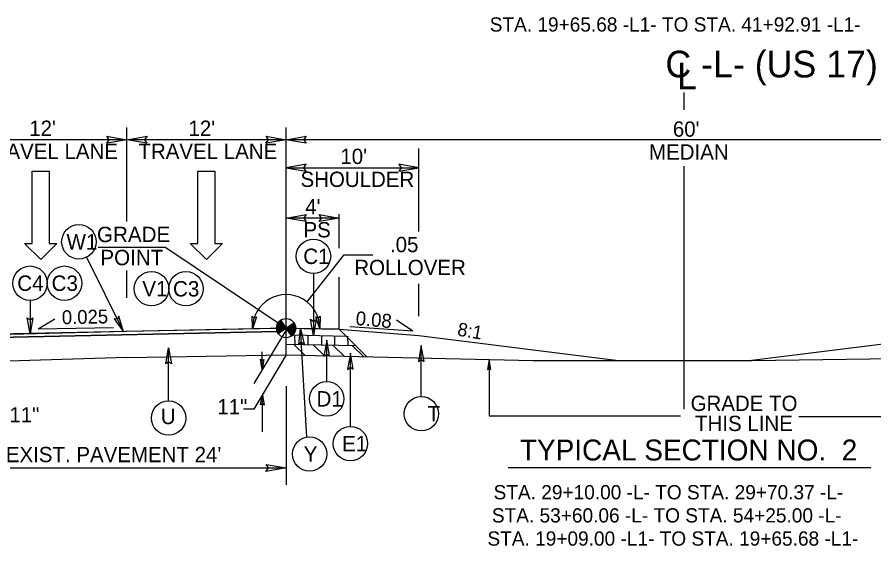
# Model space of a CAD drawing. Extents: x 2176024 to 2177225, y 75947 to 76635.
# Drawn here: x 2176725.6 to 2176790.1, y 76497.9 to 76537.7 of the extents above; entities that cross this region are included whole.
import ezdxf

# ---------------------------------------------------------------- set-up
doc = ezdxf.new("R2010")
doc.units = 0
for name, color, linetype in [('Exist XS Ground Line', 7, 'Continuous'), ('Old_Level_1', 7, 'Continuous'), ('Old_Level_11', 7, 'Continuous'), ('Old_Level_3', 7, 'Continuous'), ('Old_Level_4', 7, 'Continuous'), ('Prop Dimension', 7, 'Continuous'), ('Typical Curb CELL', 7, 'Continuous'), ('Typical Grade Point Symbol CELL', 7, 'Continuous'), ('Typical Pavement Slope CELL', 7, 'Continuous'), ('Typical Pavement Slope Information CELL', 7, 'Continuous'), ('Typical Shoulder Slope CELL', 7, 'Continuous'), ('Typical Slope Point Local CELL', 7, 'Continuous'), ('Typical Terminator CELL', 7, 'Continuous'), ('Typical Text General CELL', 7, 'Continuous'), ('Typical Text Label CELL', 7, 'Continuous')]:
    doc.layers.add(name, color=color, linetype=linetype)

msp = doc.modelspace()

# ---------------------------------------------------------------- linework, layer by layer
at = {"layer": 'Exist XS Ground Line'}
for q in [(2176721.841, 76511.705), (2176745.841, 76512.258)]:
    msp.add_line((2176733.841, 76512.056), q, dxfattribs=at)
at = {"layer": 'Old_Level_1'}
for p, q in [((2176746.512, 76513.046), (2176746.507, 76513.755)), ((2176747.51, 76513.024), (2176747.504, 76513.734)), ((2176748.543, 76513.003), (2176748.537, 76513.713)), ((2176749.524, 76512.981), (2176749.518, 76513.693)), ((2176750.505, 76512.957), (2176750.499, 76513.672)), ((2176747.287, 76512.213), (2176746.426, 76513.051)), ((2176748.725, 76512.193), (2176747.886, 76513.018)), ((2176750.204, 76512.16), (2176749.36, 76512.991)), ((2176751.694, 76512.117), (2176750.851, 76512.946)), ((2176762.567, 76503.771), (2176789.888, 76503.771))]:
    msp.add_line(p, q, dxfattribs=at)
at = {"layer": 'Old_Level_11'}
for p, q in [((2176736.776, 76520.349), (2176731.682, 76520.349)), ((2176736.776, 76520.349), (2176745.841, 76514.272)), ((2176730.802, 76519.616), (2176733.596, 76514.003)), ((2176750.159, 76519.771), (2176747.406, 76516.265)), ((2176752.368, 76519.771), (2176750.159, 76519.771)), ((2176747.896, 76518.39), (2176747.896, 76513.73)), ((2176726.55, 76516.363), (2176726.55, 76513.839)), ((2176747.41, 76506.064), (2176746.927, 76514.253)), ((2176748.905, 76510.241), (2176748.905, 76513.374)), ((2176736.983, 76508.794), (2176736.983, 76512.793)), ((2176756.029, 76509.115), (2176756.029, 76512.957)), ((2176750.685, 76506.87), (2176750.685, 76512.374))]:
    msp.add_line(p, q, dxfattribs=at)
for points in [[(2176726.757, 76515.039), (2176726.55, 76513.839), (2176726.337, 76515.045), (2176726.55, 76514.892)], [(2176732.876, 76514.985), (2176733.596, 76514.003), (2176733.249, 76515.178), (2176733.127, 76514.946)], [(2176748.103, 76514.93), (2176747.896, 76513.73), (2176747.683, 76514.937), (2176747.896, 76514.783)], [(2176746.791, 76513.043), (2176746.927, 76514.253), (2176747.211, 76513.061), (2176746.989, 76513.201)], [(2176749.111, 76512.174), (2176748.905, 76513.374), (2176748.691, 76512.168), (2176748.905, 76512.321)], [(2176736.776, 76511.593), (2176736.983, 76512.793), (2176737.196, 76511.587), (2176736.983, 76511.74)], [(2176756.236, 76511.757), (2176756.029, 76512.957), (2176755.816, 76511.75), (2176756.029, 76511.903)], [(2176750.892, 76511.174), (2176750.685, 76512.374), (2176750.472, 76511.167), (2176750.685, 76511.32)]]:
    msp.add_lwpolyline(points, close=True, dxfattribs=at)
for centre in [(2176730.224, 76520.777), (2176747.902, 76519.686), (2176726.55, 76517.659), (2176729.143, 76517.659), (2176735.699, 76517.238), (2176738.291, 76517.238), (2176748.905, 76508.945), (2176736.983, 76507.498), (2176756.029, 76507.819), (2176750.685, 76505.574), (2176747.61, 76504.783)]:
    msp.add_circle(centre, 1.296, dxfattribs=at)
msp.add_arc((2176745.841, 76514.272), 2.534, 358.80651, 181.19349, dxfattribs=at)
at = {"layer": 'Old_Level_4'}
for p, q in [((2176726.703, 76520.662), (2176726.703, 76526.094)), ((2176726.703, 76526.094), (2176727.984, 76526.094)), ((2176727.984, 76526.094), (2176727.984, 76520.662)), ((2176739.181, 76520.662), (2176739.181, 76526.094)), ((2176739.181, 76526.094), (2176740.462, 76526.094)), ((2176740.462, 76526.094), (2176740.462, 76520.662)), ((2176727.363, 76519.44), (2176726.121, 76520.662)), ((2176726.121, 76520.662), (2176726.703, 76520.662)), ((2176728.566, 76520.662), (2176727.363, 76519.44)), ((2176727.984, 76520.662), (2176728.566, 76520.662)), ((2176739.841, 76519.44), (2176738.599, 76520.662)), ((2176738.599, 76520.662), (2176739.181, 76520.662)), ((2176741.044, 76520.662), (2176739.841, 76519.44)), ((2176740.462, 76520.662), (2176741.044, 76520.662))]:
    msp.add_line(p, q, dxfattribs=at)
at = {"layer": 'Prop Dimension'}
for p, q in [((2176775.841, 76530.729), (2176775.841, 76532.022)), ((2176733.841, 76522.302), (2176733.841, 76529.396)), ((2176745.841, 76514.023), (2176745.841, 76529.396)), ((2176733.841, 76528.468), (2176721.947, 76528.468)), ((2176745.841, 76528.468), (2176733.947, 76528.468)), ((2176805.841, 76528.468), (2176745.841, 76528.468)), ((2176755.841, 76521.567), (2176755.841, 76527.807)), ((2176745.841, 76526.36), (2176755.841, 76526.36)), ((2176775.841, 76508.156), (2176775.841, 76526.488)), ((2176749.841, 76520.301), (2176749.841, 76522.853)), ((2176749.841, 76522.57), (2176745.841, 76522.57)), ((2176733.841, 76516.546), (2176733.841, 76518.616)), ((2176749.841, 76514.189), (2176749.841, 76518.104)), ((2176755.841, 76515.183), (2176755.841, 76517.62)), ((2176745.841, 76514.695), (2176745.841, 76516.31)), ((2176745.826, 76514.1), (2176743.4, 76510.092)), ((2176744.037, 76511.167), (2176744.037, 76512.495)), ((2176745.84, 76512.258), (2176743.414, 76508.163)), ((2176761.143, 76511.908), (2176761.143, 76507.674)), ((2176745.841, 76509.904), (2176745.841, 76502.468)), ((2176744.051, 76506.463), (2176744.051, 76509.239)), ((2176743.414, 76508.163), (2176742.634, 76508.163)), ((2176761.143, 76507.674), (2176775.557, 76507.674)), ((2176784.475, 76507.615), (2176797.385, 76507.615)), ((2176721.841, 76503.745), (2176745.841, 76503.745))]:
    msp.add_line(p, q, dxfattribs=at)
at = {"layer": 'Typical Curb CELL'}
for p in [(2176745.84, 76512.258), (2176745.841, 76512.258)]:
    msp.add_line(p, (2176745.841, 76514.272), dxfattribs=at)
at = {"layer": 'Typical Grade Point Symbol CELL'}
for p, q in [((2176745.429, 76514.864), (2176745.841, 76514.272)), ((2176745.841, 76514.272), (2176746.432, 76514.684)), ((2176745.248, 76513.862), (2176745.841, 76514.272)), ((2176745.841, 76514.272), (2176745.248, 76513.862)), ((2176746.253, 76513.681), (2176745.841, 76514.272))]:
    msp.add_line(p, q, dxfattribs=at)
for points in [[(2176745.596, 76514.625), (2176745.12, 76514.294)], [(2176745.604, 76514.613), (2176745.12, 76514.276)], [(2176745.612, 76514.601), (2176745.12, 76514.259)], [(2176745.587, 76514.637), (2176745.121, 76514.312)], [(2176745.62, 76514.589), (2176745.121, 76514.242)], [(2176745.629, 76514.577), (2176745.121, 76514.224)], [(2176745.579, 76514.648), (2176745.122, 76514.33)], [(2176745.637, 76514.566), (2176745.123, 76514.208)], [(2176745.571, 76514.66), (2176745.124, 76514.349)], [(2176745.645, 76514.554), (2176745.124, 76514.191)], [(2176745.563, 76514.672), (2176745.126, 76514.368)], [(2176745.653, 76514.542), (2176745.126, 76514.175)], [(2176745.554, 76514.684), (2176745.128, 76514.387)], [(2176745.661, 76514.53), (2176745.129, 76514.16)], [(2176745.546, 76514.696), (2176745.132, 76514.408)], [(2176745.67, 76514.518), (2176745.132, 76514.144)], [(2176745.678, 76514.506), (2176745.135, 76514.129)], [(2176745.538, 76514.708), (2176745.137, 76514.429)], [(2176745.686, 76514.495), (2176745.138, 76514.113)], [(2176745.694, 76514.483), (2176745.141, 76514.098)], [(2176745.53, 76514.719), (2176745.142, 76514.45)], [(2176745.703, 76514.471), (2176745.145, 76514.083)], [(2176745.521, 76514.731), (2176745.148, 76514.471)], [(2176745.711, 76514.459), (2176745.149, 76514.068)], [(2176745.513, 76514.743), (2176745.154, 76514.493)], [(2176745.719, 76514.447), (2176745.154, 76514.054)], [(2176745.727, 76514.435), (2176745.159, 76514.04)], [(2176745.505, 76514.755), (2176745.162, 76514.516)], [(2176745.736, 76514.424), (2176745.164, 76514.026)], [(2176745.744, 76514.412), (2176745.169, 76514.012)], [(2176745.497, 76514.767), (2176745.171, 76514.54)], [(2176745.752, 76514.4), (2176745.175, 76513.998)], [(2176745.489, 76514.779), (2176745.181, 76514.564)], [(2176745.48, 76514.79), (2176745.194, 76514.591)], [(2176745.472, 76514.802), (2176745.208, 76514.618)], [(2176745.464, 76514.814), (2176745.225, 76514.648)], [(2176745.456, 76514.826), (2176745.244, 76514.679)], [(2176745.447, 76514.838), (2176745.271, 76514.715)], [(2176745.439, 76514.85), (2176745.305, 76514.756)], [(2176745.431, 76514.861), (2176745.366, 76514.817)], [(2176746.436, 76514.679), (2176746.436, 76514.679), (2176745.844, 76514.267)], [(2176746.444, 76514.667), (2176745.853, 76514.255)], [(2176746.451, 76514.654), (2176745.861, 76514.243)], [(2176746.46, 76514.642), (2176745.869, 76514.232)], [(2176746.466, 76514.63), (2176745.877, 76514.22)], [(2176746.473, 76514.617), (2176745.886, 76514.208)], [(2176746.48, 76514.604), (2176745.894, 76514.196)], [(2176746.487, 76514.591), (2176745.902, 76514.184)], [(2176746.494, 76514.579), (2176745.91, 76514.172)], [(2176746.5, 76514.565), (2176745.919, 76514.161)], [(2176746.505, 76514.551), (2176745.927, 76514.149)], [(2176746.511, 76514.538), (2176745.935, 76514.137)], [(2176746.517, 76514.524), (2176745.943, 76514.125)], [(2176746.521, 76514.51), (2176745.952, 76514.113)], [(2176746.526, 76514.496), (2176745.96, 76514.101)], [(2176746.531, 76514.481), (2176745.968, 76514.09)], [(2176746.535, 76514.467), (2176745.976, 76514.078)], [(2176746.539, 76514.452), (2176745.984, 76514.066)], [(2176746.542, 76514.437), (2176745.993, 76514.054)], [(2176746.545, 76514.421), (2176746.001, 76514.042)], [(2176746.548, 76514.406), (2176746.009, 76514.03)], [(2176745.76, 76514.388), (2176745.18, 76513.985)], [(2176745.769, 76514.376), (2176745.186, 76513.971)], [(2176745.777, 76514.364), (2176745.193, 76513.958)], [(2176745.785, 76514.353), (2176745.199, 76513.945)], [(2176745.793, 76514.341), (2176745.206, 76513.932)], [(2176745.801, 76514.329), (2176745.212, 76513.919)], [(2176745.81, 76514.317), (2176745.219, 76513.906)], [(2176745.818, 76514.305), (2176745.228, 76513.894)], [(2176745.826, 76514.293), (2176745.235, 76513.882)], [(2176745.834, 76514.282), (2176745.243, 76513.87), (2176745.243, 76513.87)], [(2176746.551, 76514.39), (2176746.017, 76514.019)], [(2176746.554, 76514.375), (2176746.026, 76514.007)], [(2176746.556, 76514.358), (2176746.034, 76513.995)], [(2176746.558, 76514.342), (2176746.042, 76513.983)], [(2176746.559, 76514.325), (2176746.05, 76513.971)], [(2176746.561, 76514.309), (2176746.059, 76513.959)], [(2176746.561, 76514.292), (2176746.067, 76513.948)], [(2176746.562, 76514.274), (2176746.075, 76513.936)], [(2176746.561, 76514.256), (2176746.083, 76513.924)], [(2176746.561, 76514.239), (2176746.092, 76513.912)], [(2176746.56, 76514.221), (2176746.1, 76513.9)], [(2176746.558, 76514.201), (2176746.108, 76513.888)], [(2176746.555, 76514.182), (2176746.116, 76513.877)], [(2176746.553, 76514.163), (2176746.124, 76513.865)], [(2176746.55, 76514.143), (2176746.133, 76513.853)], [(2176746.546, 76514.123), (2176746.141, 76513.841)], [(2176746.541, 76514.102), (2176746.149, 76513.829)], [(2176746.535, 76514.08), (2176746.157, 76513.817)], [(2176746.529, 76514.058), (2176746.166, 76513.806)], [(2176746.521, 76514.035), (2176746.174, 76513.794)], [(2176746.512, 76514.012), (2176746.182, 76513.782)], [(2176746.502, 76513.987), (2176746.19, 76513.77)], [(2176746.491, 76513.961), (2176746.199, 76513.758)], [(2176746.478, 76513.935), (2176746.207, 76513.746)], [(2176746.461, 76513.906), (2176746.215, 76513.735)], [(2176746.442, 76513.875), (2176746.223, 76513.723)], [(2176746.417, 76513.84), (2176746.232, 76513.711)], [(2176746.384, 76513.8), (2176746.24, 76513.699)], [(2176746.332, 76513.746), (2176746.248, 76513.687)]]:
    msp.add_lwpolyline(points, dxfattribs=at)
msp.add_circle((2176745.841, 76514.273), 0.721, dxfattribs=at)
for start, end in [(124.8249, 214.8249), (304.8249, 34.8249)]:
    msp.add_arc((2176745.841, 76514.273), 0.721, start, end, dxfattribs=at)
at = {"layer": 'Typical Pavement Slope CELL'}
for p, q in [((2176745.841, 76514.272), (2176721.841, 76513.772)), ((2176745.17, 76514.008), (2176721.841, 76513.522)), ((2176745.841, 76514.272), (2176745.841, 76514.022)), ((2176746.345, 76513.759), (2176750.358, 76513.675)), ((2176749.841, 76514.189), (2176751.948, 76512.094)), ((2176745.84, 76513.064), (2176751.082, 76512.955)), ((2176745.841, 76512.258), (2176764.449, 76511.833)), ((2176764.449, 76511.833), (2176780.941, 76511.822)), ((2176780.941, 76511.822), (2176799.228, 76512.11))]:
    msp.add_line(p, q, dxfattribs=at)
at = {"layer": 'Typical Pavement Slope Information CELL'}
for p, q in [((2176727.155, 76514.208), (2176728.416, 76514.97)), ((2176755.38, 76514.046), (2176754.156, 76514.866)), ((2176727.155, 76514.208), (2176732.84, 76514.322)), ((2176755.38, 76514.046), (2176750.634, 76514.36))]:
    msp.add_line(p, q, dxfattribs=at)
at = {"layer": 'Typical Shoulder Slope CELL'}
for p, q in [((2176733.841, 76514.022), (2176721.841, 76513.72)), ((2176749.841, 76514.189), (2176755.841, 76513.709)), ((2176755.841, 76513.709), (2176770.886, 76511.828)), ((2176795.842, 76513.684), (2176780.941, 76511.822))]:
    msp.add_line(p, q, dxfattribs=at)
at = {"layer": 'Typical Slope Point Local CELL'}
for p, q in [((2176733.841, 76514.022), (2176721.841, 76513.772)), ((2176721.841, 76513.522), (2176745.17, 76514.008)), ((2176745.12, 76514.257), (2176733.841, 76514.022)), ((2176745.121, 76514.224), (2176745.121, 76514.224)), ((2176745.126, 76514.175), (2176745.126, 76514.175)), ((2176745.141, 76514.098), (2176745.141, 76514.098)), ((2176745.145, 76514.083), (2176745.145, 76514.083)), ((2176745.154, 76514.054), (2176745.154, 76514.054)), ((2176745.841, 76514.272), (2176749.841, 76514.189)), ((2176746.345, 76513.759), (2176750.358, 76513.675)), ((2176746.384, 76513.8), (2176746.384, 76513.799)), ((2176746.417, 76513.84), (2176746.416, 76513.84)), ((2176746.442, 76513.875), (2176746.441, 76513.874)), ((2176746.461, 76513.906), (2176746.46, 76513.905)), ((2176746.478, 76513.935), (2176746.477, 76513.934)), ((2176746.491, 76513.961), (2176746.49, 76513.961)), ((2176746.521, 76514.035), (2176746.521, 76514.035)), ((2176746.529, 76514.058), (2176746.529, 76514.058)), ((2176746.541, 76514.102), (2176746.541, 76514.102)), ((2176746.546, 76514.123), (2176746.545, 76514.123)), ((2176746.55, 76514.143), (2176746.55, 76514.143)), ((2176746.553, 76514.163), (2176746.553, 76514.163)), ((2176746.56, 76514.221), (2176746.559, 76514.22)), ((2176749.841, 76514.189), (2176746.561, 76514.257)), ((2176746.561, 76514.239), (2176746.561, 76514.238)), ((2176750.358, 76513.675), (2176749.841, 76514.189))]:
    msp.add_line(p, q, dxfattribs=at)
for points in [[(2176745.121, 76514.224), (2176745.121, 76514.224)], [(2176745.126, 76514.175), (2176745.126, 76514.175)], [(2176745.141, 76514.098), (2176745.141, 76514.098)], [(2176745.145, 76514.083), (2176745.145, 76514.083)], [(2176745.154, 76514.054), (2176745.154, 76514.054)], [(2176746.384, 76513.8), (2176746.384, 76513.8)], [(2176746.417, 76513.84), (2176746.417, 76513.84)], [(2176746.441, 76513.875), (2176746.442, 76513.875)], [(2176746.461, 76513.906), (2176746.461, 76513.906)], [(2176746.477, 76513.935), (2176746.478, 76513.935)], [(2176746.49, 76513.962), (2176746.491, 76513.961)], [(2176746.521, 76514.035), (2176746.521, 76514.035)], [(2176746.529, 76514.058), (2176746.529, 76514.058)], [(2176746.541, 76514.102), (2176746.541, 76514.102)], [(2176746.546, 76514.123), (2176746.546, 76514.123)], [(2176746.55, 76514.143), (2176746.55, 76514.143)], [(2176746.553, 76514.163), (2176746.553, 76514.163)], [(2176746.559, 76514.221), (2176746.56, 76514.221)], [(2176746.561, 76514.239), (2176746.561, 76514.239)]]:
    msp.add_lwpolyline(points, dxfattribs=at)
for start, end in [(181.25594, 183.8761), (183.88947, 185.20212), (185.20212, 186.51209), (186.51209, 187.80941), (187.82447, 194.07544), (194.0907, 195.29679), (195.29757, 196.50552), (196.50552, 197.7127), (197.71542, 200.09456), (200.09456, 201.54788), (314.44987, 318.89175), (318.962, 323.02167), (323.07123, 326.39495), (326.45695, 329.32655), (329.36485, 331.96034), (332.04132, 334.37636), (334.38027, 340.73102), (340.73681, 342.64285), (342.64598, 344.4557), (344.4557, 346.24045), (346.26481, 347.94552), (347.9775, 349.59802), (349.59837, 351.20379), (351.21961, 354.28369), (354.28369, 355.7778), (355.81267, 357.23939), (358.64252, 358.74502), (357.26518, 358.64252)]:
    msp.add_arc((2176745.841, 76514.273), 0.721, start, end, dxfattribs=at)
at = {"layer": 'Typical Terminator CELL'}
for points in [[(2176732.331, 76528.728), (2176733.841, 76528.468), (2176732.323, 76528.2), (2176732.516, 76528.468)], [(2176735.35, 76528.208), (2176733.841, 76528.468), (2176735.359, 76528.736), (2176735.166, 76528.468)], [(2176744.331, 76528.728), (2176745.841, 76528.468), (2176744.323, 76528.2), (2176744.516, 76528.468)], [(2176747.35, 76528.208), (2176745.841, 76528.468), (2176747.359, 76528.736), (2176747.166, 76528.468)], [(2176747.35, 76526.62), (2176745.841, 76526.36), (2176747.359, 76526.091), (2176747.166, 76526.36)], [(2176754.331, 76526.1), (2176755.841, 76526.36), (2176754.323, 76526.628), (2176754.516, 76526.36)], [(2176747.35, 76522.31), (2176745.841, 76522.57), (2176747.359, 76522.839), (2176747.166, 76522.57)], [(2176748.331, 76522.83), (2176749.841, 76522.57), (2176748.323, 76522.302), (2176748.516, 76522.57)], [(2176743.609, 76515.122), (2176743.307, 76514.22), (2176743.286, 76515.177), (2176743.432, 76515.033)], [(2176748.397, 76515.171), (2176748.374, 76514.22), (2176748.072, 76515.128), (2176748.254, 76515.034)], [(2176744.17, 76511.921), (2176744.037, 76511.167), (2176743.905, 76511.926), (2176744.039, 76511.83)], [(2176761.273, 76511.154), (2176761.143, 76511.908), (2176761.009, 76511.149), (2176761.143, 76511.246)], [(2176743.919, 76508.484), (2176744.051, 76509.239), (2176744.183, 76508.479), (2176744.049, 76508.576)], [(2176744.331, 76504.005), (2176745.841, 76503.745), (2176744.323, 76503.476), (2176744.516, 76503.745)]]:
    msp.add_lwpolyline(points, close=True, dxfattribs=at)

# ---------------------------------------------------------------- texts
at = {"layer": 'Old_Level_11'}
for s, rotation, p in [('GRADE', 0.00015, (2176731.593, 76520.754)), ('W1', 359.99974, (2176729.293, 76520.197)), ('C1', 0.00026, (2176747.133, 76519.106)), ('POINT', 0.00015, (2176731.846, 76519.014)), ('C4', 0.00026, (2176725.584, 76517.079)), ('C3', 0.00026, (2176728.17, 76517.079)), ('V1', 0.00026, (2176735.005, 76516.658)), ('C3', 0.00026, (2176737.318, 76516.658)), ('D1', 0.00026, (2176748.132, 76508.365)), ('U', 0.00026, (2176736.397, 76507.043)), ('T', 0.00026, (2176756.486, 76507.239)), ('E1', 0.00026, (2176750.057, 76504.994)), ('Y', 0.00026, (2176747.165, 76504.203))]:
    msp.add_text(s, height=1.16, rotation=rotation, dxfattribs=at).set_placement(p)
for p in [(2176740.655, 76507.773), (2176724.988, 76507.163)]:
    msp.add_text('11"', height=1.1533, dxfattribs=at).set_placement(p)
at = {"layer": 'Old_Level_3'}
msp.add_text('TYPICAL SECTION NO.  2', height=1.5766, rotation=0.00002, dxfattribs=at).set_placement((2176763.454, 76504.299))
at = {"layer": 'Typical Pavement Slope Information CELL'}
for s, rotation, p in [('0.025', 1.14574, (2176728.951, 76514.566)), ('0.08', 354.76446, (2176751.047, 76514.516))]:
    msp.add_text(s, height=1.0429, rotation=rotation, dxfattribs=at).set_placement(p)
at = {"layer": 'Typical Slope Point Local CELL'}
msp.add_text('8:1', height=1.0064, rotation=350.16835, dxfattribs=at).set_placement((2176758.694, 76513.723))
at = {"layer": 'Typical Text General CELL'}
for s, height, p in [("12' ", 1.1533, (2176726.485, 76528.757)), ("12' ", 1.1533, (2176738.485, 76528.757)), ("60'", 1.1533, (2176774.979, 76528.698)), ('TRAVEL LANE', 1.15334, (2176722.715, 76527.027)), ('TRAVEL LANE', 1.15334, (2176734.715, 76527.027)), ('MEDIAN', 1.1533, (2176773.186, 76526.968)), ("10'", 1.1533, (2176749.928, 76526.64)), ('SHOULDER', 1.1533, (2176746.926, 76524.91)), ("4'", 1.1533, (2176747.279, 76522.841)), ('PS', 1.1533, (2176747.149, 76521.111)), ('GRADE TO ', 1.1533, (2176776.316, 76508.029)), ('THIS LINE', 1.1533, (2176776.652, 76506.517)), ("EXIST. PAVEMENT 24'", 1.15334, (2176724.722, 76504.172))]:
    msp.add_text(s, height=height, dxfattribs=at).set_placement(p)
for s, p in [('.05', (2176753.666, 76519.997)), ('ROLLOVER', (2176750.98, 76518.267))]:
    msp.add_text(s, height=1.1533, rotation=360, dxfattribs=at).set_placement(p)
at = {"layer": 'Typical Text Label CELL'}
for s, height, p in [('STA. 19+65.68 -L1- TO STA. 41+92.91 -L1-', 1.0742, (2176761.182, 76536.618)), ('C -L- (US 17) & -L1-  (US 17)', 2.01314, (2176774.42, 76533.164)), ('STA. 29+10.00 -L- TO STA. 29+70.37 -L-', 1.0742, (2176761.473, 76501.372)), ('STA. 53+60.06 -L- TO STA. 54+25.00 -L-', 1.0742, (2176761.345, 76499.627)), ('STA. 19+09.00 -L1- TO STA. 19+65.68 -L1-', 1.0742, (2176761.01, 76497.881))]:
    msp.add_text(s, height=height, dxfattribs=at).set_placement(p)
msp.add_text('L', height=2.013, rotation=359.9469, dxfattribs=at).set_placement((2176775.298, 76532.263))

doc.saveas('drawing.dxf')
